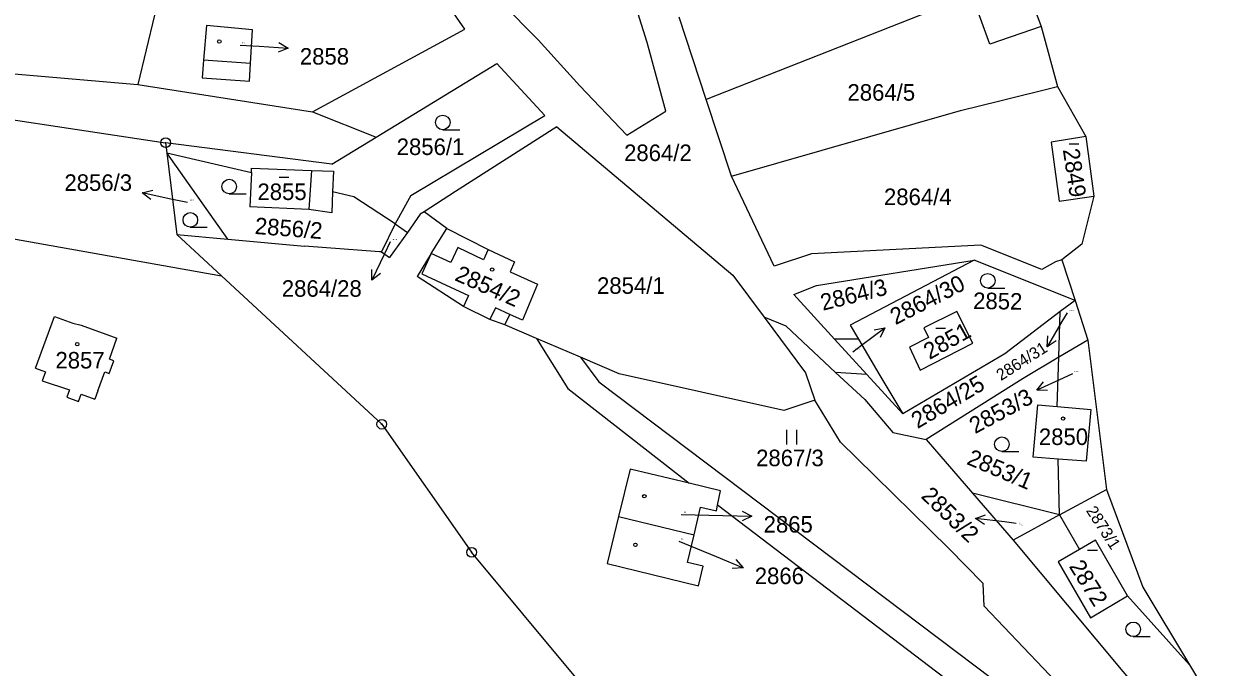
# Model space of a CAD drawing. Extents: x -736345 to -729997, y -1130177 to -1122501.
# Drawn here: x -735140.9 to -735018.3, y -1124160.8 to -1124094.6 of the extents above; entities that cross this region are included whole.
import ezdxf

# ---------------------------------------------------------------- set-up
doc = ezdxf.new("R2010")
doc.units = 0
for name, color, linetype in [('Vrstva 1', 7, 'Continuous'), ('Vrstva 13', 7, 'Continuous'), ('Vrstva 16', 7, 'Continuous'), ('Vrstva 18', 7, 'Continuous'), ('Vrstva 19', 7, 'Continuous'), ('Vrstva 25', 7, 'Continuous'), ('Vrstva 4', 7, 'Continuous')]:
    doc.layers.add(name, color=color, linetype=linetype)

msp = doc.modelspace()

# ---------------------------------------------------------------- linework, layer by layer
at = {"layer": 'Vrstva 1'}
for points in [[(-735095.63, -1124095.12), (-735104.83, -1124081.82)], [(-735076.86, -1124096.48), (-735080.52, -1124084.92)], [(-735043.49, -1124091.55), (-735070.81, -1124102.37)], [(-735088.09, -1124096.21), (-735091.85, -1124092.41)], [(-735041.67, -1124096.67), (-735043.29, -1124092.12)], [(-735127.51, -1124093.67), (-735129.23, -1124100.8)], [(-735070.81, -1124102.37), (-735073.6, -1124093.88)], [(-735122.15, -1124094.74), (-735122.48, -1124098.32)], [(-735117.45, -1124095.18), (-735122.15, -1124094.74)], [(-735117.63, -1124098.67), (-735117.45, -1124095.18)], [(-735111.27, -1124103.62), (-735095.63, -1124095.12)], [(-735036.39, -1124094.86), (-735041.67, -1124096.67)], [(-735083.79, -1124100.94), (-735088.09, -1124096.21)], [(-735074.95, -1124103.57), (-735076.86, -1124096.48)], [(-735151.5, -1124098.9), (-735129.23, -1124100.8)], [(-735122.48, -1124098.32), (-735122.61, -1124100.14)], [(-735117.76, -1124100.49), (-735117.63, -1124098.67)], [(-735104.73, -1124106.23), (-735092.34, -1124098.66)], [(-735092.34, -1124098.66), (-735087.39, -1124104)], [(-735122.61, -1124100.14), (-735117.76, -1124100.49)], [(-735129.23, -1124100.8), (-735111.27, -1124103.62)], [(-735078.98, -1124106.02), (-735083.79, -1124100.94)], [(-735040.62, -1124102.48), (-735034.71, -1124101.02)], [(-735152.7, -1124102.85), (-735126.37, -1124106.81)], [(-735068.21, -1124110.25), (-735070.81, -1124102.37)], [(-735044.69, -1124103.49), (-735040.62, -1124102.48)], [(-735111.27, -1124103.62), (-735104.73, -1124106.23)], [(-735101.16, -1124112.23), (-735087.39, -1124104)], [(-735078.98, -1124106.02), (-735074.95, -1124103.57)], [(-735068.21, -1124110.25), (-735044.69, -1124103.49)], [(-735086.17, -1124105.17), (-735096.57, -1124111.83)], [(-735086.17, -1124105.17), (-735068.06, -1124120.44)], [(-735109.3, -1124109.02), (-735104.73, -1124106.23)], [(-735031.8, -1124106.18), (-735035.36, -1124106.74)], [(-735035.36, -1124106.74), (-735034.53, -1124112.81)], [(-735109.3, -1124109.02), (-735126.37, -1124106.81)], [(-735126.37, -1124106.81), (-735126.24, -1124107.84)], [(-735119.96, -1124116.71), (-735126.24, -1124107.84)], [(-735126.24, -1124107.84), (-735117.55, -1124109.88)], [(-735126.24, -1124107.84), (-735125.22, -1124116.23)], [(-735117.55, -1124109.88), (-735117.71, -1124113.4)], [(-735117.55, -1124109.88), (-735117.53, -1124109.43)], [(-735117.53, -1124109.43), (-735111.38, -1124109.65)], [(-735111.38, -1124109.65), (-735109.13, -1124109.73)], [(-735109.13, -1124109.73), (-735109.2, -1124111.85)], [(-735063.81, -1124119.49), (-735068.21, -1124110.25)], [(-735109.2, -1124111.85), (-735109.28, -1124114.03)], [(-735107.04, -1124112.36), (-735109.2, -1124111.85)], [(-735102.79, -1124115.15), (-735107.04, -1124112.36)], [(-735101.16, -1124112.23), (-735102.79, -1124115.15)], [(-735096.57, -1124111.83), (-735099.81, -1124113.91)], [(-735034.53, -1124112.81), (-735030.96, -1124112.32)], [(-735111.64, -1124113.69), (-735117.71, -1124113.4)], [(-735109.28, -1124114.03), (-735111.64, -1124113.69)], [(-735099.81, -1124113.91), (-735100.21, -1124114.16)], [(-735097.48, -1124115.63), (-735099.81, -1124113.91)], [(-735149.72, -1124115.31), (-735120.62, -1124120.49)], [(-735102.79, -1124115.15), (-735104.18, -1124118.04)], [(-735102.79, -1124115.15), (-735101.52, -1124116.03)], [(-735100.21, -1124114.16), (-735101.52, -1124116.03)], [(-735120.62, -1124120.49), (-735125.22, -1124116.23)], [(-735125.22, -1124116.23), (-735119.96, -1124116.71)], [(-735101.52, -1124116.03), (-735103.28, -1124118.52)], [(-735099.06, -1124118.2), (-735097.48, -1124115.63)], [(-735097.48, -1124115.63), (-735093.22, -1124117.8)], [(-735119.96, -1124116.71), (-735112.08, -1124117.44)], [(-735104.4, -1124118.02), (-735112.08, -1124117.44)], [(-735042.58, -1124117.34), (-735060, -1124118.23)], [(-735036.31, -1124119.85), (-735042.58, -1124117.34)], [(-735104.18, -1124118.04), (-735104.4, -1124118.02)], [(-735104.18, -1124118.04), (-735103.35, -1124118.61)], [(-735103.28, -1124118.52), (-735103.35, -1124118.61)], [(-735099.06, -1124118.2), (-735100.51, -1124120.56)], [(-735093.22, -1124117.8), (-735090.51, -1124119.07)], [(-735060, -1124118.23), (-735063.81, -1124119.49)], [(-735059.49, -1124121.49), (-735043.28, -1124118.87)], [(-735043.28, -1124118.87), (-735056.03, -1124125.59)], [(-735032.89, -1124123.02), (-735043.28, -1124118.87)], [(-735034.25, -1124118.86), (-735034.91, -1124119.05)], [(-735090.51, -1124119.07), (-735090.97, -1124120.09)], [(-735090.97, -1124120.09), (-735088.16, -1124121.35)], [(-735034.91, -1124119.05), (-735036.31, -1124119.85)], [(-735120.62, -1124120.49), (-735104.15, -1124135.76)], [(-735095.76, -1124123.65), (-735100.51, -1124120.56)], [(-735088.16, -1124121.35), (-735089.7, -1124125.05)], [(-735068.06, -1124120.44), (-735064.84, -1124124.76)], [(-735061.82, -1124122.41), (-735059.49, -1124121.49)], [(-735057.61, -1124127.03), (-735061.82, -1124122.41)], [(-735093.03, -1124125), (-735095.76, -1124123.65)], [(-735032.89, -1124123.02), (-735034.42, -1124124.18)], [(-735139.74, -1124130.01), (-735137.79, -1124124.67)], [(-735137.79, -1124124.67), (-735135.89, -1124125.37)], [(-735091.49, -1124125.53), (-735093.03, -1124125)], [(-735091.49, -1124125.53), (-735091, -1124124.46)], [(-735089.7, -1124125.05), (-735091, -1124124.46)], [(-735064.84, -1124124.76), (-735060.59, -1124130.48)], [(-735062.59, -1124125.68), (-735064.84, -1124124.76)], [(-735045.05, -1124124.15), (-735048.45, -1124125.86)], [(-735043.42, -1124127.43), (-735045.05, -1124124.15)], [(-735034.42, -1124124.18), (-735040.12, -1124128.51)], [(-735034.57, -1124128.88), (-735034.42, -1124124.18)], [(-735135.89, -1124125.37), (-735135.03, -1124125.59)], [(-735135.03, -1124125.59), (-735131.37, -1124126.91)], [(-735088.24, -1124126.93), (-735091.49, -1124125.53)], [(-735057.51, -1124130.43), (-735062.59, -1124125.68)], [(-735056.03, -1124125.59), (-735055.17, -1124127.03)], [(-735048.45, -1124125.86), (-735047.96, -1124126.84)], [(-735132.15, -1124129.06), (-735131.37, -1124126.91)], [(-735088.24, -1124126.93), (-735085.04, -1124132.08)], [(-735083.73, -1124128.87), (-735088.24, -1124126.93)], [(-735054.3, -1124130.66), (-735057.61, -1124127.03)], [(-735055.17, -1124127.03), (-735057.61, -1124127.03)], [(-735055.17, -1124127.03), (-735052.96, -1124130.76)], [(-735047.96, -1124126.84), (-735049.92, -1124127.82)], [(-735048.83, -1124130.19), (-735043.42, -1124127.43)], [(-735031.6, -1124127.12), (-735034.57, -1124128.88)], [(-735040.12, -1124128.51), (-735050.61, -1124134.71)], [(-735049.92, -1124127.82), (-735048.83, -1124130.19)], [(-735139.74, -1124130.01), (-735138.72, -1124130.38)], [(-735132.16, -1124130.54), (-735131.68, -1124129.23)], [(-735131.68, -1124129.23), (-735132.15, -1124129.06)], [(-735083.73, -1124128.87), (-735081.84, -1124131.41)], [(-735079.74, -1124130.58), (-735083.73, -1124128.87)], [(-735034.57, -1124128.88), (-735038.24, -1124131.06)], [(-735034.73, -1124133.94), (-735034.57, -1124128.88)], [(-735138.72, -1124130.38), (-735139.06, -1124131.31)], [(-735133.34, -1124132.34), (-735132.63, -1124130.37)], [(-735132.63, -1124130.37), (-735132.16, -1124130.54)], [(-735062.83, -1124134.34), (-735079.74, -1124130.58)], [(-735060.59, -1124130.48), (-735059.64, -1124133.29)], [(-735054.3, -1124130.66), (-735057.51, -1124130.43)], [(-735057.51, -1124130.43), (-735054.51, -1124133.23)], [(-735050.61, -1124134.71), (-735054.3, -1124130.66)], [(-735052.96, -1124130.76), (-735050.61, -1124134.71)], [(-735038.24, -1124131.06), (-735048.2, -1124137.35)], [(-735139.06, -1124131.31), (-735136.24, -1124132.23)], [(-735136.24, -1124132.23), (-735136.51, -1124132.97)], [(-735133.34, -1124132.34), (-735133.65, -1124133.18)], [(-735085.04, -1124132.08), (-735072.55, -1124141.83)], [(-735081.84, -1124131.41), (-735024.87, -1124174.43)], [(-735136.51, -1124132.97), (-735135.31, -1124133.41)], [(-735135.31, -1124133.41), (-735135.04, -1124132.67)], [(-735135.04, -1124132.67), (-735133.65, -1124133.18)], [(-735059.64, -1124133.29), (-735062.83, -1124134.34)], [(-735057.02, -1124137.6), (-735059.64, -1124133.29)], [(-735054.51, -1124133.23), (-735051.62, -1124136.63)], [(-735037.22, -1124139.15), (-735036.73, -1124133.76)], [(-735036.73, -1124133.76), (-735034.73, -1124133.94)], [(-735034.73, -1124133.94), (-735031.28, -1124134.25)], [(-735031.28, -1124134.25), (-735031.76, -1124139.56)], [(-735104.15, -1124135.76), (-735094.92, -1124148.94)], [(-735051.62, -1124136.63), (-735048.2, -1124137.35)], [(-735048.2, -1124137.35), (-735043.44, -1124142.85)], [(-735055.37, -1124139.22), (-735057.02, -1124137.6)], [(-735045.88, -1124148.55), (-735055.37, -1124139.22)], [(-735034.64, -1124139.34), (-735037.22, -1124139.15)], [(-735031.76, -1124139.56), (-735034.64, -1124139.34)], [(-735034.5, -1124145.1), (-735034.64, -1124139.34)], [(-735078.62, -1124140.38), (-735079.81, -1124145.24)], [(-735072.55, -1124141.83), (-735078.62, -1124140.38)], [(-735069.33, -1124142.6), (-735072.55, -1124141.83)], [(-735069.64, -1124144.1), (-735069.33, -1124142.6)], [(-735043.44, -1124142.85), (-735039.26, -1124147.68)], [(-735034.5, -1124145.1), (-735043.44, -1124142.85)], [(-735034.5, -1124145.1), (-735029.68, -1124142.49)], [(-735072.05, -1124147.14), (-735071.39, -1124144.29)], [(-735071.39, -1124144.29), (-735069.76, -1124144.67)], [(-735069.76, -1124144.67), (-735069.64, -1124144.1)], [(-735027.58, -1124176.15), (-735069.64, -1124144.1)], [(-735079.81, -1124145.24), (-735081, -1124150.1)], [(-735079.81, -1124145.24), (-735072.05, -1124147.14)], [(-735034.5, -1124145.1), (-735039.26, -1124147.68)], [(-735034.5, -1124145.1), (-735032.45, -1124148.64)], [(-735072.72, -1124150), (-735072.05, -1124147.14)], [(-735039.26, -1124147.68), (-735025.22, -1124164.53)], [(-735030.8, -1124147.69), (-735032.45, -1124148.64)], [(-735027.5, -1124153.41), (-735030.8, -1124147.69)], [(-735073.83, -1124174.3), (-735094.92, -1124148.94)], [(-735042.33, -1124152.14), (-735045.88, -1124148.55)], [(-735032.45, -1124148.64), (-735034.64, -1124149.91)], [(-735081, -1124150.1), (-735071.6, -1124152.4)], [(-735071.12, -1124150.37), (-735072.72, -1124150)], [(-735071.6, -1124152.4), (-735071.12, -1124150.37)], [(-735034.64, -1124149.91), (-735031.31, -1124155.68)], [(-735042.23, -1124154.47), (-735042.33, -1124152.14)], [(-735034.17, -1124162.97), (-735042.23, -1124154.47)], [(-735031.31, -1124155.68), (-735027.5, -1124153.41)], [(-735027.5, -1124153.41), (-735021.13, -1124160.52)]]:
    msp.add_lwpolyline(points, dxfattribs=at)
at = {"layer": 'Vrstva 13'}
for points in [[(-735038.07, -1124090.31), (-735036.39, -1124094.86)], [(-735036.39, -1124094.86), (-735034.71, -1124101.02)], [(-735034.71, -1124101.02), (-735031.8, -1124106.18)], [(-735031.8, -1124106.18), (-735030.96, -1124112.32)], [(-735030.96, -1124112.32), (-735032.21, -1124117.24)], [(-735032.21, -1124117.24), (-735034.25, -1124118.86)], [(-735034.25, -1124118.86), (-735032.89, -1124123.02)], [(-735032.89, -1124123.02), (-735031.6, -1124127.12)], [(-735031.6, -1124127.12), (-735029.68, -1124142.49)], [(-735029.68, -1124142.49), (-735025.92, -1124152.54)], [(-735025.92, -1124152.54), (-735021.13, -1124160.52)], [(-735021.13, -1124160.52), (-735018.3, -1124165.24)]]:
    msp.add_lwpolyline(points, dxfattribs=at)
at = {"layer": 'Vrstva 16'}
for points in [[(-735118.72, -1124096.78), (-735116.76, -1124096.89)], [(-735124.11, -1124112.97), (-735125.84, -1124112.6)], [(-735103.28, -1124117.01), (-735103.87, -1124118.25)], [(-735033.72, -1124124.3), (-735034.25, -1124125.21)], [(-735055.74, -1124128.3), (-735054.85, -1124127.64)], [(-735033.17, -1124130.58), (-735034.12, -1124131.02)], [(-735073.38, -1124145.06), (-735069.11, -1124145.15)], [(-735038.96, -1124145.97), (-735040.17, -1124145.82)], [(-735073.61, -1124147.79), (-735069.79, -1124149.37)]]:
    msp.add_lwpolyline(points, dxfattribs=at)
at = {"layer": 'Vrstva 25'}
for points in [[(-735116.76, -1124096.89), (-735113.766, -1124097.067)], [(-735114.734, -1124096.51), (-735113.766, -1124097.067), (-735114.794, -1124097.507)], [(-735097.88, -1124105.47), (-735096.13, -1124105.47)], [(-735033.5, -1124106.91), (-735032.5, -1124106.91)], [(-735114.69, -1124110.36), (-735113.69, -1124110.36)], [(-735127.9, -1124112.662), (-735128.771, -1124111.961), (-735127.687, -1124111.686)], [(-735125.84, -1124112.6), (-735128.771, -1124111.961)], [(-735119.83, -1124112.06), (-735118.08, -1124112.06)], [(-735123.83, -1124115.49), (-735122.08, -1124115.49)], [(-735103.87, -1124118.25), (-735105.17, -1124120.953)], [(-735104.286, -1124120.268), (-735105.17, -1124120.953), (-735105.187, -1124119.835)], [(-735041.87, -1124121.76), (-735040.12, -1124121.76)], [(-735054.85, -1124127.64), (-735052.439, -1124125.856)], [(-735053.54, -1124126.049), (-735052.439, -1124125.856), (-735052.945, -1124126.853)], [(-735047.22, -1124125.87), (-735046.22, -1124125.87)], [(-735034.25, -1124125.21), (-735035.763, -1124127.8)], [(-735034.827, -1124127.189), (-735035.763, -1124127.8), (-735035.69, -1124126.684)], [(-735034.12, -1124131.02), (-735036.845, -1124132.273)], [(-735035.728, -1124132.309), (-735036.845, -1124132.273), (-735036.145, -1124131.401)], [(-735062.527, -1124137.845), (-735062.527, -1124136.345)], [(-735061.493, -1124137.845), (-735061.493, -1124136.345)], [(-735040.42, -1124138.57), (-735038.67, -1124138.57)], [(-735067.1, -1124144.692), (-735066.111, -1124145.212), (-735067.121, -1124145.691)], [(-735069.11, -1124145.15), (-735066.111, -1124145.212)], [(-735042.216, -1124146.068), (-735043.146, -1124145.45), (-735042.092, -1124145.077)], [(-735040.17, -1124145.82), (-735043.146, -1124145.45)], [(-735069.79, -1124149.37), (-735067.019, -1124150.518)], [(-735031.61, -1124148.73), (-735030.61, -1124148.73)], [(-735067.751, -1124149.673), (-735067.019, -1124150.518), (-735068.134, -1124150.597)], [(-735026.92, -1124157.61), (-735025.17, -1124157.61)]]:
    msp.add_lwpolyline(points, dxfattribs=at)
for centre, radius in [((-735120.85, -1124096.39), 0.175), ((-735097.88, -1124104.72), 0.75), ((-735126.37, -1124106.81), 0.5), ((-735126.37, -1124106.81), 0.032), ((-735119.83, -1124111.31), 0.75), ((-735123.83, -1124114.74), 0.75), ((-735092.81, -1124119.86), 0.175), ((-735041.87, -1124121.01), 0.75), ((-735135.45, -1124127.53), 0.175), ((-735104.15, -1124135.76), 0.5), ((-735104.15, -1124135.76), 0.032), ((-735034.13, -1124135.18), 0.175), ((-735040.42, -1124137.82), 0.75), ((-735077.17, -1124143.17), 0.175), ((-735094.92, -1124148.94), 0.5), ((-735078.08, -1124148.17), 0.175), ((-735094.92, -1124148.94), 0.032), ((-735026.92, -1124156.86), 0.75)]:
    msp.add_circle(centre, radius, dxfattribs=at)
at = {"layer": 'Vrstva 4'}
for points in [[(-735117.63, -1124098.67), (-735122.48, -1124098.32)], [(-735111.38, -1124109.65), (-735111.64, -1124113.69)], [(-735096.35, -1124117.6), (-735097.07, -1124119.14)], [(-735093.71, -1124118.84), (-735096.35, -1124117.6)], [(-735099.06, -1124118.2), (-735100.04, -1124120.29)], [(-735097.07, -1124119.14), (-735099.06, -1124118.2)], [(-735093.22, -1124117.8), (-735093.71, -1124118.84)], [(-735100.04, -1124120.29), (-735098.05, -1124121.22)], [(-735098.05, -1124121.22), (-735095.24, -1124122.51)], [(-735095.24, -1124122.51), (-735095.76, -1124123.65)], [(-735092.48, -1124123.79), (-735093.03, -1124125)], [(-735091, -1124124.46), (-735092.48, -1124123.79)]]:
    msp.add_lwpolyline(points, dxfattribs=at)

# ---------------------------------------------------------------- texts
at = {"layer": 'Vrstva 16'}
for s, p in [('2858', (-735112.57, -1124098.77)), ('2856/3', (-735136.767, -1124111.76)), ('2864/28', (-735114.427, -1124122.65)), ('2865', (-735064.91, -1124146.91)), ('2866', (-735065.82, -1124152.21))]:
    msp.add_text(s, height=1.7, dxfattribs=at).set_placement(p)
for s, height, rotation, p in [('2864/30', 1.7, 27.10022, (-735051.354, -1124125.581)), ('2864/31', 1.2, 32.50026, (-735040.514, -1124131.333)), ('2853/3', 1.7, 28.30023, (-735043.184, -1124136.794)), ('2853/2', 1.7, 316.20251, (-735048.821, -1124143.253))]:
    msp.add_text(s, height=height, rotation=rotation, dxfattribs=at).set_placement(p)
at = {"layer": 'Vrstva 18'}
for s, height, p in [('2864/5', 1.7, (-735056.29, -1124102.48)), ('2856/1', 1.7, (-735102.62, -1124108.07)), ('2864/2', 1.7, (-735079.25, -1124108.69)), ('2864/4', 1.7, (-735052.54, -1124113.22)), ('2856/3', 0.1, (-735123.91, -1124112.77)), ('2864/28', 0.1, (-735103.08, -1124116.81)), ('2864/31', 0.1, (-735033.52, -1124124.1)), ('2864/30', 0.1, (-735055.54, -1124128.1)), ('2853/3', 0.1, (-735032.97, -1124130.38)), ('2867/3', 1.7, (-735065.68, -1124140.08))]:
    msp.add_text(s, height=height, dxfattribs=at).set_placement(p)
for s, height, rotation, p in [('2856/2', 1.7, 355.60283, (-735117.246, -1124116.186)), ('2864/3', 1.7, 14.10011, (-735058.825, -1124124.098)), ('2852', 1.7, 359.10286, (-735043.387, -1124123.904)), ('2864/25', 1.7, 30.60024, (-735049.09, -1124136.267)), ('2853/1', 1.7, 337.10268, (-735044.138, -1124139.834)), ('2873/1', 1.2, 302.80241, (-735031.814, -1124144.649)), ('2853/2', 0.1, 317.60253, (-735038.678, -1124145.958))]:
    msp.add_text(s, height=height, rotation=rotation, dxfattribs=at).set_placement(p)
at = {"layer": 'Vrstva 19'}
for s, height, p in [('2858', 0.1, (-735118.52, -1124096.58)), ('2855', 1.7, (-735116.93, -1124112.7)), ('2854/1', 1.7, (-735082.03, -1124122.35)), ('2857', 1.7, (-735137.69, -1124130.03)), ('2850', 1.7, (-735036.62, -1124137.9)), ('2865', 0.1, (-735073.18, -1124144.86)), ('2866', 0.1, (-735073.41, -1124147.59))]:
    msp.add_text(s, height=height, dxfattribs=at).set_placement(p)
for s, rotation, p in [('2849', 278.50221, (-735034.163, -1124107.518)), ('2854/2', 336.00267, (-735096.756, -1124120.919)), ('2851', 29.30023, (-735047.854, -1124129.158)), ('2872', 302.1024, (-735033.575, -1124150.383))]:
    msp.add_text(s, height=1.7, rotation=rotation, dxfattribs=at).set_placement(p)

doc.saveas('drawing.dxf')
